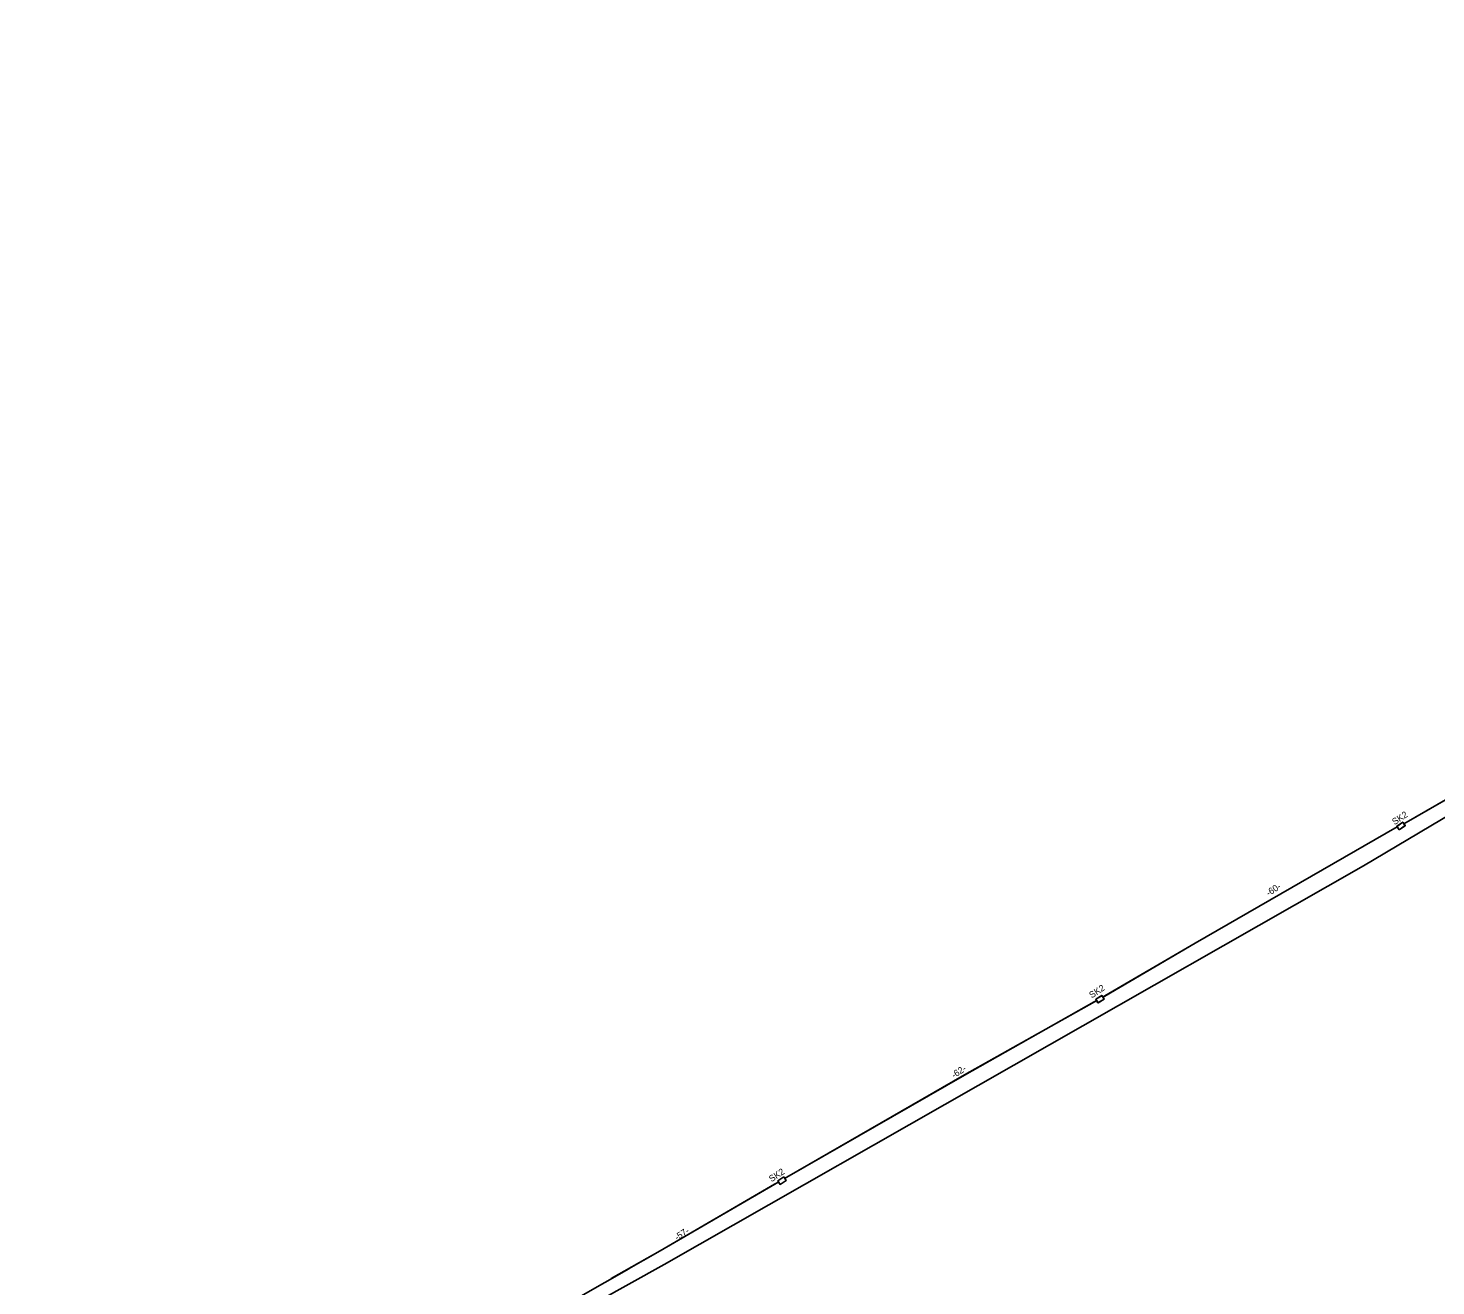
# Model space of a CAD drawing. Extents: x 6494530 to 6506885, y 5884901 to 5892312.
# Drawn here: x 6499554.1 to 6499786.5, y 5889258.9 to 5889466.7 of the extents above; entities that cross this region are included whole.
import ezdxf

# ---------------------------------------------------------------- set-up
doc = ezdxf.new("R2010")
doc.units = 0
for name, color, linetype in [('kabel do infokiosku_OTK', 7, 'Continuous'), ('studnie do wyrysu', 7, 'Continuous'), ('trasa kanalizacji do wyrysu', 7, 'Continuous'), ('trasa kanalizacji wyrys', 7, 'Continuous')]:
    doc.layers.add(name, color=color, linetype=linetype)

msp = doc.modelspace()

# ---------------------------------------------------------------- linework, layer by layer
at = {"layer": 'kabel do infokiosku_OTK'}
msp.add_lwpolyline([(6499554.09, 5889170.71), (6499581.11, 5889186.16), (6499594.81, 5889200.14), (6499622.14, 5889239.87), (6499631.44, 5889247.03), (6499659.1, 5889262.44), (6499774.56, 5889328.27), (6499883.18, 5889392.84), (6499905.24, 5889421.74), (6499917.64, 5889419.55), (6499951.4, 5889466.66)], dxfattribs=at)
at = {"layer": 'studnie do wyrysu'}
for points in [[(6499780.47, 5889334.25), (6499781.46, 5889334.93), (6499781.06, 5889335.51), (6499780.07, 5889334.82), (6499780.47, 5889334.25)], [(6499780.47, 5889334.25), (6499781.46, 5889334.93), (6499781.06, 5889335.51), (6499780.07, 5889334.82), (6499780.47, 5889334.25)], [(6499780.5, 5889334.25), (6499781.48, 5889334.94), (6499781.08, 5889335.51), (6499780.1, 5889334.83), (6499780.5, 5889334.25)], [(6499780.5, 5889334.25), (6499781.48, 5889334.94), (6499781.08, 5889335.51), (6499780.1, 5889334.83), (6499780.5, 5889334.25)], [(6499780.5, 5889334.25), (6499781.48, 5889334.94), (6499781.08, 5889335.51), (6499780.1, 5889334.83), (6499780.5, 5889334.25)], [(6499780.5, 5889334.25), (6499781.48, 5889334.94), (6499781.08, 5889335.51), (6499780.1, 5889334.83), (6499780.5, 5889334.25)], [(6499731.4, 5889306.89), (6499730.37, 5889306.27), (6499730.73, 5889305.67), (6499731.76, 5889306.29), (6499731.4, 5889306.89)], [(6499731.4, 5889306.89), (6499730.37, 5889306.27), (6499730.73, 5889305.67), (6499731.76, 5889306.29), (6499731.4, 5889306.89)], [(6499731.43, 5889306.89), (6499730.4, 5889306.27), (6499730.76, 5889305.67), (6499731.79, 5889306.29), (6499731.43, 5889306.89)], [(6499731.43, 5889306.89), (6499730.4, 5889306.27), (6499730.76, 5889305.67), (6499731.79, 5889306.29), (6499731.43, 5889306.89)], [(6499731.43, 5889306.89), (6499730.4, 5889306.27), (6499730.76, 5889305.67), (6499731.79, 5889306.29), (6499731.43, 5889306.89)], [(6499731.43, 5889306.89), (6499730.4, 5889306.27), (6499730.76, 5889305.67), (6499731.79, 5889306.29), (6499731.43, 5889306.89)], [(6499678.87, 5889276.92), (6499677.87, 5889276.25), (6499678.26, 5889275.67), (6499679.25, 5889276.33), (6499678.87, 5889276.92)], [(6499678.87, 5889276.92), (6499677.87, 5889276.25), (6499678.26, 5889275.67), (6499679.25, 5889276.33), (6499678.87, 5889276.92)], [(6499678.89, 5889276.92), (6499677.9, 5889276.26), (6499678.28, 5889275.67), (6499679.28, 5889276.34), (6499678.89, 5889276.92)], [(6499678.89, 5889276.92), (6499677.9, 5889276.26), (6499678.28, 5889275.67), (6499679.28, 5889276.34), (6499678.89, 5889276.92)], [(6499678.89, 5889276.92), (6499677.9, 5889276.26), (6499678.28, 5889275.67), (6499679.28, 5889276.34), (6499678.89, 5889276.92)], [(6499678.89, 5889276.92), (6499677.9, 5889276.26), (6499678.28, 5889275.67), (6499679.28, 5889276.34), (6499678.89, 5889276.92)]]:
    msp.add_lwpolyline(points, dxfattribs=at)
at = {"layer": 'trasa kanalizacji do wyrysu'}
for points in [[(6499781.23, 5889335.25), (6499818.68, 5889356.78), (6499818.92, 5889356.93)], [(6499781.23, 5889335.25), (6499818.68, 5889356.78), (6499818.92, 5889356.93)], [(6499781.26, 5889335.26), (6499818.71, 5889356.79), (6499818.95, 5889356.93)], [(6499781.26, 5889335.26), (6499818.71, 5889356.79), (6499818.95, 5889356.93)], [(6499781.26, 5889335.26), (6499818.71, 5889356.79), (6499818.95, 5889356.93)], [(6499781.26, 5889335.26), (6499818.71, 5889356.79), (6499818.95, 5889356.93)], [(6499731.56, 5889306.62), (6499731.87, 5889306.79), (6499746.77, 5889315.52), (6499780.13, 5889334.74)], [(6499731.56, 5889306.62), (6499731.87, 5889306.79), (6499746.77, 5889315.52), (6499780.13, 5889334.74)], [(6499731.59, 5889306.63), (6499731.9, 5889306.8), (6499746.8, 5889315.53), (6499780.15, 5889334.75)], [(6499731.59, 5889306.63), (6499731.9, 5889306.8), (6499746.8, 5889315.53), (6499780.15, 5889334.75)], [(6499731.59, 5889306.63), (6499731.9, 5889306.8), (6499746.8, 5889315.53), (6499780.15, 5889334.75)], [(6499731.59, 5889306.63), (6499731.9, 5889306.8), (6499746.8, 5889315.53), (6499780.15, 5889334.75)], [(6499679.03, 5889276.67), (6499679.35, 5889276.85), (6499708.68, 5889293.74), (6499730.14, 5889305.83), (6499730.51, 5889306.04)], [(6499679.03, 5889276.67), (6499679.35, 5889276.85), (6499708.68, 5889293.74), (6499730.14, 5889305.83), (6499730.51, 5889306.04)], [(6499679.06, 5889276.68), (6499679.38, 5889276.86), (6499708.71, 5889293.75), (6499730.17, 5889305.84), (6499730.54, 5889306.04)], [(6499679.06, 5889276.68), (6499679.38, 5889276.86), (6499708.71, 5889293.75), (6499730.17, 5889305.84), (6499730.54, 5889306.04)], [(6499679.06, 5889276.68), (6499679.38, 5889276.86), (6499708.71, 5889293.75), (6499730.17, 5889305.84), (6499730.54, 5889306.04)], [(6499679.06, 5889276.68), (6499679.38, 5889276.86), (6499708.71, 5889293.75), (6499730.17, 5889305.84), (6499730.54, 5889306.04)], [(6499650.38, 5889260.12), (6499658.44, 5889264.71), (6499677.35, 5889275.7), (6499677.99, 5889276.07)], [(6499650.38, 5889260.12), (6499658.44, 5889264.71), (6499677.35, 5889275.7), (6499677.99, 5889276.07)], [(6499650.41, 5889260.12), (6499658.47, 5889264.72), (6499677.38, 5889275.71), (6499678.02, 5889276.08)], [(6499650.41, 5889260.12), (6499658.47, 5889264.72), (6499677.38, 5889275.71), (6499678.02, 5889276.08)], [(6499650.41, 5889260.12), (6499658.47, 5889264.72), (6499677.38, 5889275.71), (6499678.02, 5889276.08)], [(6499650.41, 5889260.12), (6499658.47, 5889264.72), (6499677.38, 5889275.71), (6499678.02, 5889276.08)]]:
    msp.add_lwpolyline(points, dxfattribs=at)
at = {"layer": 'trasa kanalizacji wyrys'}
msp.add_lwpolyline([(6499632.67, 5889250), (6499653.27, 5889261.75)], dxfattribs=at)

# ---------------------------------------------------------------- texts
at = {"layer": 'studnie do wyrysu'}
for p in [(6499779.74, 5889335), (6499729.72, 5889306.38), (6499676.84, 5889276.02)]:
    msp.add_text('SK2', height=1.075, rotation=33.4183, dxfattribs=at).set_placement(p)
at = {"layer": 'trasa kanalizacji do wyrysu'}
for s, p in [('-60-', (6499758.92, 5889323.24)), ('-62-', (6499706.96, 5889293.16)), ('-57-', (6499661.24, 5889266.36))]:
    msp.add_text(s, height=1.075, rotation=33.2051, dxfattribs=at).set_placement(p)

doc.saveas('drawing.dxf')
